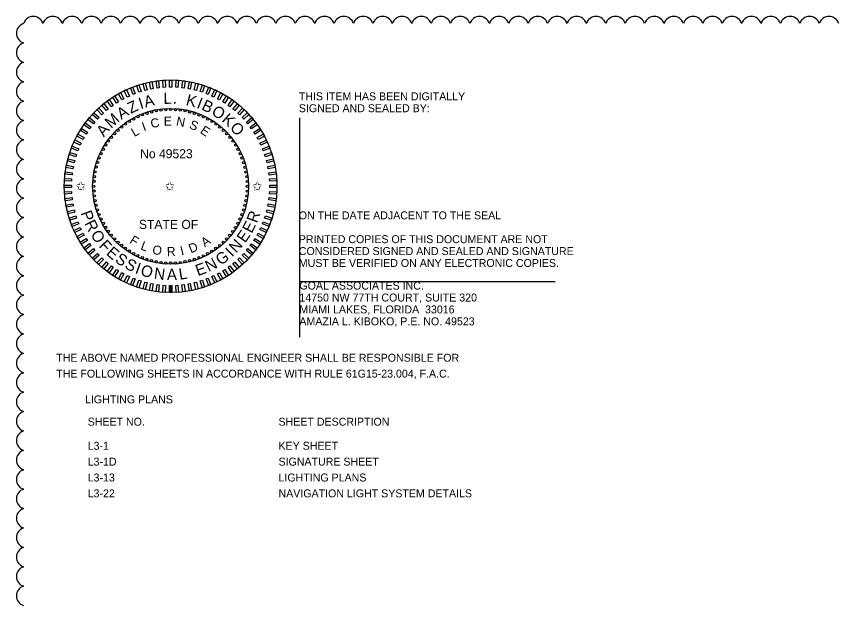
# Model space of a CAD drawing. Extents: x -811 to -795.3, y -2245.7 to -2235.4.
# Drawn here: x -810.85 to -803.6, y -2240.63 to -2235.44 of the extents above; entities that cross this region are included whole.
import ezdxf

# ---------------------------------------------------------------- set-up
doc = ezdxf.new("R2010")
doc.units = 0
for name, color, linetype in [('PlotBorder_dp', 7, 'Continuous'), ('ScratchEle_dp', 7, 'Continuous'), ('TextMinor', 7, 'Continuous'), ('TextMisc', 7, 'Continuous'), ('TextShtNo', 7, 'Continuous'), ('TextTitle', 7, 'Continuous')]:
    doc.layers.add(name, color=color, linetype=linetype)

msp = doc.modelspace()

# ---------------------------------------------------------------- linework, layer by layer
at = {"layer": 'ScratchEle_dp'}
for centre, start, end in [((-810.7011, -2235.5263), 17.5, 162.5), ((-810.53, -2235.5263), 17.5, 162.5), ((-810.3589, -2235.5263), 17.5, 162.5), ((-810.1878, -2235.5263), 17.5, 162.5), ((-810.0167, -2235.5263), 17.5, 162.5), ((-809.8455, -2235.5263), 17.5, 162.5), ((-809.6744, -2235.5263), 17.5, 162.5), ((-809.5033, -2235.5263), 17.5, 162.5), ((-809.3322, -2235.5263), 17.5, 162.5), ((-809.161, -2235.5263), 17.5, 162.5), ((-808.9899, -2235.5263), 17.5, 162.5), ((-808.8188, -2235.5263), 17.5, 162.5), ((-808.6477, -2235.5263), 17.5, 162.5), ((-808.4766, -2235.5263), 17.5, 162.5), ((-808.3054, -2235.5263), 17.5, 162.5), ((-808.1343, -2235.5263), 17.5, 162.5), ((-807.9632, -2235.5263), 17.5, 162.5), ((-807.7921, -2235.5263), 17.5, 162.5), ((-807.6209, -2235.5263), 17.5, 162.5), ((-807.4498, -2235.5263), 17.5, 162.5), ((-807.2787, -2235.5263), 17.5, 162.5), ((-807.1076, -2235.5263), 17.5, 162.5), ((-806.9364, -2235.5263), 17.5, 162.5), ((-806.7653, -2235.5263), 17.5, 162.5), ((-806.5942, -2235.5263), 17.5, 162.5), ((-806.4231, -2235.5263), 17.5, 162.5), ((-806.252, -2235.5263), 17.5, 162.5), ((-806.0808, -2235.5263), 17.5, 162.5), ((-805.9097, -2235.5263), 17.5, 162.5), ((-805.7386, -2235.5263), 17.5, 162.5), ((-805.5675, -2235.5263), 17.5, 162.5), ((-805.3963, -2235.5263), 17.5, 162.5), ((-805.2252, -2235.5263), 17.5, 162.5), ((-805.0541, -2235.5263), 17.5, 162.5), ((-804.883, -2235.5263), 17.5, 162.5), ((-804.7119, -2235.5263), 17.5, 162.5), ((-804.5407, -2235.5263), 17.5, 162.5), ((-804.3696, -2235.5263), 17.5, 162.5), ((-804.1985, -2235.5263), 17.5, 162.5), ((-804.0274, -2235.5263), 17.5, 162.5), ((-803.8562, -2235.5263), 17.5, 162.5), ((-803.6851, -2235.5263), 17.5, 162.5), ((-810.7597, -2235.5849), 107.5, 252.5), ((-810.7597, -2235.7561), 107.5, 252.5), ((-810.7597, -2235.9272), 107.5, 252.5), ((-810.7597, -2236.0983), 107.5, 252.5), ((-810.7597, -2236.2694), 107.5, 252.5), ((-810.7597, -2236.4405), 107.5, 252.5), ((-810.7597, -2236.6117), 107.5, 252.5), ((-810.7597, -2236.7828), 107.5, 252.5), ((-810.7597, -2236.9539), 107.5, 252.5), ((-810.7597, -2237.125), 107.5, 252.5), ((-810.7597, -2237.2962), 107.5, 252.5), ((-810.7597, -2237.4673), 107.5, 252.5), ((-810.7597, -2237.6384), 107.5, 252.5), ((-810.7597, -2237.8095), 107.5, 252.5), ((-810.7597, -2237.9806), 107.5, 252.5), ((-810.7597, -2238.1518), 107.5, 252.5), ((-810.7597, -2238.3229), 107.5, 252.5), ((-810.7597, -2238.494), 107.5, 252.5), ((-810.7597, -2238.6651), 107.5, 252.5), ((-810.7597, -2238.8363), 107.5, 252.5), ((-810.7597, -2239.0074), 107.5, 252.5), ((-810.7597, -2239.1785), 107.5, 252.5), ((-810.7597, -2239.3496), 107.5, 252.5), ((-810.7597, -2239.5207), 107.5, 252.5), ((-810.7597, -2239.6919), 107.5, 252.5), ((-810.7597, -2239.863), 107.5, 252.5), ((-810.7597, -2240.0341), 107.5, 252.5), ((-810.7597, -2240.2052), 107.5, 252.5), ((-810.7597, -2240.3764), 107.5, 252.5), ((-810.7597, -2240.5475), 107.5, 252.5)]:
    msp.add_arc(centre, 0.0897, start, end, dxfattribs=at)
at = {"layer": 'TextMinor'}
for radius in [0.9375, 0.6875]:
    msp.add_circle((-809.4901, -2236.9348), radius, dxfattribs=at)
at = {"layer": 'TextShtNo'}
for p, q in [((-809.5001, -2237.8724), (-809.5003, -2237.8099)), ((-809.4901, -2237.8723), (-809.4903, -2237.8098)), ((-809.4801, -2237.8723), (-809.4803, -2237.8098))]:
    msp.add_line(p, q, dxfattribs=at)
for points in [[(-809.7508, -2236.0995), (-809.77, -2236.1057), (-809.7893, -2236.0463), (-809.7701, -2236.0401)], [(-809.6979, -2236.0847), (-809.7174, -2236.0898), (-809.7329, -2236.0293), (-809.7134, -2236.0243)], [(-809.6441, -2236.0734), (-809.6639, -2236.0772), (-809.6756, -2236.0158), (-809.6558, -2236.012)], [(-809.5897, -2236.0654), (-809.6097, -2236.0679), (-809.6175, -2236.006), (-809.5975, -2236.0035)], [(-809.5349, -2236.0609), (-809.555, -2236.0621), (-809.559, -2235.9998), (-809.5388, -2235.9986)], [(-809.4799, -2236.0598), (-809.5001, -2236.0598), (-809.5001, -2235.9974), (-809.4799, -2235.9974)], [(-809.425, -2236.0622), (-809.4452, -2236.0609), (-809.4412, -2235.9986), (-809.4211, -2235.9998)], [(-809.3703, -2236.068), (-809.3904, -2236.0654), (-809.3825, -2236.0035), (-809.3625, -2236.006)], [(-809.3162, -2236.0772), (-809.336, -2236.0734), (-809.3243, -2236.0121), (-809.3045, -2236.0159)], [(-809.2626, -2236.0898), (-809.2822, -2236.0848), (-809.2667, -2236.0243), (-809.2471, -2236.0293)], [(-809.21, -2236.1058), (-809.2292, -2236.0995), (-809.2099, -2236.0401), (-809.1907, -2236.0464)], [(-809.9027, -2236.1631), (-809.9204, -2236.1728), (-809.9505, -2236.1181), (-809.9328, -2236.1084)], [(-809.8535, -2236.1387), (-809.8717, -2236.1473), (-809.8983, -2236.0908), (-809.8801, -2236.0822)], [(-809.8028, -2236.1175), (-809.8215, -2236.1249), (-809.8445, -2236.0669), (-809.8258, -2236.0594)], [(-809.1585, -2236.125), (-809.1773, -2236.1176), (-809.1543, -2236.0595), (-809.1355, -2236.0669)], [(-809.1083, -2236.1474), (-809.1266, -2236.1388), (-809.1, -2236.0823), (-809.0817, -2236.0909)], [(-809.0596, -2236.1729), (-809.0773, -2236.1632), (-809.0473, -2236.1085), (-809.0296, -2236.1182)], [(-809.9962, -2236.2209), (-810.0125, -2236.2328), (-810.0492, -2236.1823), (-810.0329, -2236.1704)], [(-809.9504, -2236.1906), (-809.9674, -2236.2014), (-810.0009, -2236.1486), (-809.9838, -2236.1378)], [(-809.0127, -2236.2015), (-809.0297, -2236.1906), (-808.9962, -2236.1379), (-808.9792, -2236.1487)], [(-808.9676, -2236.2329), (-808.9839, -2236.221), (-808.9472, -2236.1705), (-808.9308, -2236.1824)], [(-810.0817, -2236.29), (-810.0964, -2236.3038), (-810.1392, -2236.2583), (-810.1244, -2236.2445)], [(-810.04, -2236.2541), (-810.0556, -2236.267), (-810.0954, -2236.2189), (-810.0798, -2236.206)], [(-808.9245, -2236.2671), (-808.9401, -2236.2542), (-808.9003, -2236.2061), (-808.8847, -2236.219)], [(-808.8837, -2236.3039), (-808.8984, -2236.2901), (-808.8557, -2236.2446), (-808.841, -2236.2584)], [(-810.1579, -2236.3692), (-810.1707, -2236.3848), (-810.2188, -2236.345), (-810.206, -2236.3294)], [(-810.121, -2236.3284), (-810.1348, -2236.3431), (-810.1804, -2236.3004), (-810.1665, -2236.2857)], [(-808.8453, -2236.3432), (-808.8591, -2236.3285), (-808.8136, -2236.2858), (-808.7998, -2236.3005)], [(-808.8094, -2236.3849), (-808.8223, -2236.3694), (-808.7742, -2236.3295), (-808.7613, -2236.3451)], [(-810.192, -2236.4122), (-810.2039, -2236.4286), (-810.2544, -2236.3919), (-810.2426, -2236.3755)], [(-808.7762, -2236.4287), (-808.7881, -2236.4124), (-808.7376, -2236.3757), (-808.7257, -2236.392)], [(-810.252, -2236.5043), (-810.2617, -2236.522), (-810.3164, -2236.492), (-810.3067, -2236.4743)], [(-810.2235, -2236.4574), (-810.2343, -2236.4744), (-810.287, -2236.4409), (-810.2762, -2236.4239)], [(-808.7459, -2236.4746), (-808.7567, -2236.4575), (-808.7039, -2236.4241), (-808.6931, -2236.4411)], [(-808.7184, -2236.5222), (-808.7281, -2236.5045), (-808.6734, -2236.4744), (-808.6637, -2236.4921)], [(-810.2775, -2236.553), (-810.2861, -2236.5713), (-810.3426, -2236.5447), (-810.334, -2236.5264)], [(-808.694, -2236.5715), (-808.7026, -2236.5532), (-808.6461, -2236.5266), (-808.6375, -2236.5449)], [(-810.3, -2236.6032), (-810.3074, -2236.622), (-810.3654, -2236.599), (-810.358, -2236.5802)], [(-808.6728, -2236.6222), (-808.6802, -2236.6034), (-808.6222, -2236.5804), (-808.6147, -2236.5992)], [(-810.3351, -2236.7073), (-810.3401, -2236.7269), (-810.4006, -2236.7114), (-810.3956, -2236.6918)], [(-810.3192, -2236.6547), (-810.3254, -2236.6739), (-810.3848, -2236.6546), (-810.3786, -2236.6354)], [(-808.6548, -2236.6741), (-808.661, -2236.6549), (-808.6016, -2236.6356), (-808.5954, -2236.6548)], [(-808.64, -2236.7271), (-808.6451, -2236.7075), (-808.5846, -2236.692), (-808.5796, -2236.7115)], [(-810.3477, -2236.7609), (-810.3515, -2236.7807), (-810.4129, -2236.769), (-810.4091, -2236.7492)], [(-808.6287, -2236.7809), (-808.6325, -2236.761), (-808.5711, -2236.7493), (-808.5673, -2236.7692)], [(-810.357, -2236.815), (-810.3595, -2236.8351), (-810.4215, -2236.8272), (-810.4189, -2236.8072)], [(-808.6207, -2236.8353), (-808.6232, -2236.8152), (-808.5613, -2236.8074), (-808.5588, -2236.8274)], [(-810.3652, -2236.9246), (-810.3652, -2236.9448), (-810.4276, -2236.9448), (-810.4276, -2236.9246)], [(-810.3628, -2236.8697), (-810.3641, -2236.8899), (-810.4264, -2236.8859), (-810.4251, -2236.8658)], [(-808.6162, -2236.89), (-808.6174, -2236.8699), (-808.5551, -2236.866), (-808.5539, -2236.8861)], [(-808.6151, -2236.945), (-808.6151, -2236.9248), (-808.5527, -2236.9248), (-808.5527, -2236.945)], [(-810.3641, -2236.9796), (-810.3628, -2236.9997), (-810.4251, -2237.0037), (-810.4264, -2236.9835)], [(-808.6175, -2236.9999), (-808.6162, -2236.9798), (-808.5539, -2236.9837), (-808.5551, -2237.0039)], [(-810.3595, -2237.0344), (-810.357, -2237.0544), (-810.4189, -2237.0622), (-810.4215, -2237.0422)], [(-808.6233, -2237.0546), (-808.6207, -2237.0346), (-808.5588, -2237.0424), (-808.5613, -2237.0624)], [(-810.3516, -2237.0888), (-810.3478, -2237.1086), (-810.4091, -2237.1203), (-810.4129, -2237.1005)], [(-808.6325, -2237.1088), (-808.6287, -2237.089), (-808.5674, -2237.1007), (-808.5712, -2237.1205)], [(-810.3402, -2237.1426), (-810.3352, -2237.1621), (-810.3957, -2237.1776), (-810.4007, -2237.1581)], [(-810.3255, -2237.1955), (-810.3192, -2237.2147), (-810.3786, -2237.234), (-810.3849, -2237.2148)], [(-808.6611, -2237.2149), (-808.6548, -2237.1957), (-808.5954, -2237.215), (-808.6017, -2237.2342)], [(-808.6451, -2237.1623), (-808.6401, -2237.1427), (-808.5796, -2237.1583), (-808.5846, -2237.1778)], [(-810.3075, -2237.2475), (-810.3, -2237.2662), (-810.3581, -2237.2892), (-810.3655, -2237.2705)], [(-808.6803, -2237.2664), (-808.6729, -2237.2476), (-808.6148, -2237.2706), (-808.6222, -2237.2894)], [(-810.2862, -2237.2982), (-810.2776, -2237.3164), (-810.3341, -2237.343), (-810.3427, -2237.3248)], [(-810.2618, -2237.3474), (-810.2521, -2237.3651), (-810.3068, -2237.3952), (-810.3165, -2237.3775)], [(-808.7282, -2237.3653), (-808.7185, -2237.3476), (-808.6638, -2237.3777), (-808.6735, -2237.3954)], [(-808.7027, -2237.3166), (-808.6941, -2237.2983), (-808.6376, -2237.3249), (-808.6462, -2237.3432)], [(-810.2344, -2237.3951), (-810.2236, -2237.4121), (-810.2763, -2237.4456), (-810.2871, -2237.4285)], [(-808.7568, -2237.4123), (-808.746, -2237.3952), (-808.6932, -2237.4287), (-808.704, -2237.4457)], [(-810.204, -2237.4409), (-810.1922, -2237.4572), (-810.2427, -2237.4939), (-810.2545, -2237.4776)], [(-810.1708, -2237.4847), (-810.158, -2237.5003), (-810.2061, -2237.5401), (-810.2189, -2237.5245)], [(-808.8224, -2237.5004), (-808.8095, -2237.4849), (-808.7614, -2237.5247), (-808.7743, -2237.5402)], [(-808.7882, -2237.4574), (-808.7763, -2237.4411), (-808.7258, -2237.4778), (-808.7377, -2237.4941)], [(-810.135, -2237.5264), (-810.1211, -2237.5411), (-810.1667, -2237.5839), (-810.1805, -2237.5691)], [(-810.0965, -2237.5657), (-810.0818, -2237.5795), (-810.1246, -2237.6251), (-810.1393, -2237.6112)], [(-808.8985, -2237.5797), (-808.8838, -2237.5658), (-808.8411, -2237.6114), (-808.8558, -2237.6252)], [(-808.8592, -2237.5412), (-808.8454, -2237.5265), (-808.7999, -2237.5693), (-808.8137, -2237.584)], [(-810.0557, -2237.6025), (-810.0402, -2237.6154), (-810.08, -2237.6635), (-810.0955, -2237.6507)], [(-810.0127, -2237.6367), (-809.9964, -2237.6486), (-810.0331, -2237.6991), (-810.0494, -2237.6873)], [(-808.984, -2237.6487), (-808.9677, -2237.6369), (-808.931, -2237.6874), (-808.9473, -2237.6992)], [(-808.9402, -2237.6155), (-808.9247, -2237.6027), (-808.8848, -2237.6508), (-808.9004, -2237.6636)], [(-809.9676, -2237.6682), (-809.9505, -2237.679), (-809.984, -2237.7317), (-810.001, -2237.7209)], [(-809.9206, -2237.6967), (-809.9029, -2237.7064), (-809.933, -2237.7611), (-809.9507, -2237.7514)], [(-809.8719, -2237.7222), (-809.8536, -2237.7308), (-809.8802, -2237.7873), (-809.8985, -2237.7787)], [(-809.1268, -2237.7309), (-809.1085, -2237.7223), (-809.0819, -2237.7788), (-809.1002, -2237.7874)], [(-809.0775, -2237.7065), (-809.0598, -2237.6968), (-809.0297, -2237.7515), (-809.0474, -2237.7612)], [(-809.0299, -2237.6791), (-809.0128, -2237.6683), (-808.9794, -2237.721), (-808.9964, -2237.7318)], [(-809.8217, -2237.7447), (-809.8029, -2237.7521), (-809.8259, -2237.8101), (-809.8447, -2237.8027)], [(-809.7702, -2237.7639), (-809.751, -2237.7701), (-809.7703, -2237.8295), (-809.7895, -2237.8233)], [(-809.7176, -2237.7798), (-809.698, -2237.7848), (-809.7136, -2237.8453), (-809.7331, -2237.8403)], [(-809.6641, -2237.7924), (-809.6443, -2237.7962), (-809.656, -2237.8576), (-809.6758, -2237.8538)], [(-809.3362, -2237.7963), (-809.3163, -2237.7925), (-809.3046, -2237.8538), (-809.3245, -2237.8576)], [(-809.2824, -2237.7849), (-809.2628, -2237.7799), (-809.2473, -2237.8404), (-809.2668, -2237.8454)], [(-809.2294, -2237.7702), (-809.2102, -2237.7639), (-809.1909, -2237.8233), (-809.2101, -2237.8296)], [(-809.1775, -2237.7522), (-809.1587, -2237.7447), (-809.1357, -2237.8028), (-809.1545, -2237.8102)], [(-809.6099, -2237.8017), (-809.5899, -2237.8042), (-809.5977, -2237.8662), (-809.6177, -2237.8636)], [(-809.5552, -2237.8075), (-809.5351, -2237.8088), (-809.539, -2237.8711), (-809.5592, -2237.8698)], [(-809.5003, -2237.8099), (-809.4801, -2237.8099), (-809.4801, -2237.8723), (-809.5003, -2237.8723)], [(-809.4453, -2237.8088), (-809.4252, -2237.8075), (-809.4213, -2237.8698), (-809.4414, -2237.8711)], [(-809.3906, -2237.8042), (-809.3705, -2237.8017), (-809.3627, -2237.8636), (-809.3827, -2237.8662)]]:
    msp.add_lwpolyline(points, close=True, dxfattribs=at)
for centre in [(-809.6581, -2236.2785), (-809.6165, -2236.2692), (-809.5745, -2236.2626), (-809.5321, -2236.2587), (-809.4896, -2236.2574), (-809.447, -2236.2587), (-809.4047, -2236.2628), (-809.3626, -2236.2695), (-809.3211, -2236.2788), (-809.816, -2236.3409), (-809.7781, -2236.3216), (-809.739, -2236.3047), (-809.6989, -2236.2903), (-809.2802, -2236.2907), (-809.2402, -2236.3051), (-809.2012, -2236.3221), (-809.1633, -2236.3414), (-809.9215, -2236.4125), (-809.8879, -2236.3864), (-809.8527, -2236.3625), (-809.1266, -2236.3631), (-809.0915, -2236.3871), (-809.0579, -2236.4132), (-809.9836, -2236.4707), (-809.9535, -2236.4406), (-809.026, -2236.4414), (-808.9959, -2236.4715), (-810.0618, -2236.5713), (-810.0379, -2236.5362), (-810.0118, -2236.5026), (-808.9678, -2236.5034), (-808.9417, -2236.5371), (-808.9178, -2236.5723), (-810.0835, -2236.608), (-808.8962, -2236.6089), (-810.1198, -2236.6849), (-810.1029, -2236.6459), (-808.8769, -2236.6469), (-808.86, -2236.686), (-810.1462, -2236.7658), (-810.1343, -2236.7249), (-808.8456, -2236.726), (-808.8338, -2236.7669), (-810.1622, -2236.8494), (-810.1555, -2236.8073), (-808.8245, -2236.8084), (-808.8179, -2236.8505), (-810.1676, -2236.9343), (-810.1662, -2236.8917), (-808.814, -2236.8928), (-810.1663, -2236.9768), (-808.814, -2236.9779), (-808.8127, -2236.9354), (-810.1623, -2237.0192), (-810.1557, -2237.0612), (-808.8248, -2237.0623), (-808.8181, -2237.0203), (-810.1464, -2237.1028), (-810.1346, -2237.1436), (-808.846, -2237.1447), (-808.8341, -2237.1038), (-810.1202, -2237.1837), (-810.1034, -2237.2228), (-808.8774, -2237.2238), (-808.8604, -2237.1847), (-810.0841, -2237.2607), (-810.0624, -2237.2974), (-808.8967, -2237.2617), (-810.0385, -2237.3326), (-810.0125, -2237.3662), (-808.9685, -2237.3671), (-808.9424, -2237.3335), (-808.9184, -2237.2983), (-809.9844, -2237.3982), (-809.9543, -2237.4283), (-809.0268, -2237.4291), (-808.9967, -2237.399), (-809.9224, -2237.4565), (-809.8888, -2237.4826), (-809.8536, -2237.5065), (-809.1276, -2237.5071), (-809.0924, -2237.4832), (-809.0587, -2237.4572), (-809.817, -2237.5282), (-809.7791, -2237.5476), (-809.74, -2237.5645), (-809.7, -2237.579), (-809.2813, -2237.5793), (-809.2413, -2237.5649), (-809.2022, -2237.5481), (-809.1642, -2237.5288), (-809.6591, -2237.5909), (-809.6176, -2237.6002), (-809.5756, -2237.6069), (-809.5332, -2237.6109), (-809.4901, -2237.6123), (-809.4481, -2237.611), (-809.4058, -2237.607), (-809.3637, -2237.6004), (-809.3222, -2237.5911)]:
    msp.add_circle(centre, 0.01, dxfattribs=at)
at = {"layer": 'TextTitle'}
for p, q in [((-808.3546, -2236.3314), (-808.3546, -2238.2661)), ((-808.3546, -2237.7761), (-806.0979, -2237.7761))]:
    msp.add_line(p, q, dxfattribs=at)

# ---------------------------------------------------------------- texts
at = {"layer": 'PlotBorder_dp'}
for s, p in [('THIS ITEM HAS BEEN DIGITALLY', (-808.3596, -2236.1763)), ('SIGNED AND SEALED BY:', (-808.3596, -2236.2813)), ('ON THE DATE ADJACENT TO THE SEAL', (-808.3596, -2237.2263)), ('PRINTED COPIES OF THIS DOCUMENT ARE NOT ', (-808.3596, -2237.4363)), ('CONSIDERED SIGNED AND SEALED AND SIGNATURE ', (-808.3596, -2237.5413)), ('MUST BE VERIFIED ON ANY ELECTRONIC COPIES.', (-808.3596, -2237.6463)), ('GOAL ASSOCIATES INC.', (-808.3546, -2237.8461)), ('14750 NW 77TH COURT, SUITE 320', (-808.3546, -2237.9511)), ('MIAMI LAKES, FLORIDA  33016', (-808.3546, -2238.0561)), ('AMAZIA L. KIBOKO, P.E. NO. 49523', (-808.3546, -2238.1611)), ('THE ABOVE NAMED PROFESSIONAL ENGINEER SHALL BE RESPONSIBLE FOR ', (-810.4987, -2238.4823)), ('THE FOLLOWING SHEETS IN ACCORDANCE WITH RULE 61G15-23.004, F.A.C.', (-810.4987, -2238.6223)), ('LIGHTING PLANS', (-810.245, -2238.8493))]:
    msp.add_text(s, height=0.07, dxfattribs=at).set_placement(p)
at = {"layer": 'TextMisc'}
for s, p in [('SHEET NO.', (-810.2215, -2239.0463)), ('SHEET DESCRIPTION', (-808.5387, -2239.0463)), ('L3-1', (-810.2215, -2239.2585)), ('KEY SHEET', (-808.5387, -2239.2585)), ('L3-1D', (-810.2215, -2239.3985)), ('SIGNATURE SHEET', (-808.5387, -2239.3985)), ('L3-13', (-810.2215, -2239.5385)), ('LIGHTING PLANS', (-808.5387, -2239.5385)), ('L3-22', (-810.2215, -2239.6785)), ('NAVIGATION LIGHT SYSTEM DETAILS', (-808.5387, -2239.6785))]:
    msp.add_text(s, height=0.07, dxfattribs=at).set_placement(p)
at = {"layer": 'TextShtNo'}
for s, height, rotation, p in [('L', 0.1, 0.99956, (-809.5521, -2236.2083)), ('K', 0.1, 345.88231, (-809.3605, -2236.2173)), ('Z', 0.1, 24.97699, (-809.842, -2236.2962)), ('I', 0.1, 17.3791, (-809.7545, -2236.2553)), ('A', 0.1, 13.84591, (-809.7121, -2236.2403)), ('.', 0.1, 354.73644, (-809.4725, -2236.2059)), ('I', 0.1, 338.30858, (-809.267, -2236.2406)), ('B', 0.1, 334.77539, (-809.2247, -2236.2557)), ('A', 0.1, 32.74398, (-809.9251, -2236.3496)), ('O', 0.1, 327.17146, (-809.1372, -2236.2968)), ('M', 0.1, 42.19, (-810.0152, -2236.4289)), ('C', 0.08, 12.20255, (-809.6579, -2236.4232)), ('E', 0.08, 0.41861, (-809.5498, -2236.3997)), ('N', 0.08, 349.29143, (-809.4455, -2236.3983)), ('K', 0.1, 318.5106, (-809.0451, -2236.3572)), ('A', 0.1, 49.957, (-810.0788, -2236.5045)), ('I', 0.08, 20.01168, (-809.7258, -2236.4508)), ('S', 0.08, 337.02207, (-809.3325, -2236.42)), ('E', 0.08, 325.86633, (-809.2358, -2236.4603)), ('O', 0.1, 310.93687, (-808.9729, -2236.4209)), ('L', 0.08, 30.40215, (-809.8093, -2236.5012)), ('P', 0.1, 289.40551, (-810.2848, -2237.1694)), ('R', 0.1, 69.5134, (-808.7299, -2237.2645)), ('R', 0.1, 296.14576, (-810.2518, -2237.2611)), ('E', 0.1, 62.47116, (-808.7761, -2237.3552)), ('O', 0.1, 303.96711, (-810.2003, -2237.3617)), ('E', 0.1, 55.42892, (-808.833, -2237.4396)), ('F', 0.1, 312.62798, (-810.1279, -2237.4637)), ('F', 0.08, 328.72408, (-809.8582, -2237.4314)), ('L', 0.08, 339.29159, (-809.7609, -2237.4905)), ('A', 0.08, 34.49917, (-809.1883, -2237.4742)), ('N', 0.1, 47.17876, (-808.9123, -2237.5287)), ('E', 0.1, 319.07833, (-810.0645, -2237.5321)), ('O', 0.08, 349.68206, (-809.6562, -2237.5302)), ('R', 0.08, 2.33977, (-809.5217, -2237.5521)), ('I', 0.08, 14.20366, (-809.3941, -2237.5454)), ('D', 0.08, 22.01279, (-809.312, -2237.5267)), ('I', 0.1, 43.64556, (-808.9499, -2237.5632)), ('S', 0.1, 326.12056, (-809.9869, -2237.598)), ('S', 0.1, 333.193, (-809.9015, -2237.6541)), ('N', 0.1, 26.86136, (-809.1544, -2237.6924)), ('G', 0.1, 35.11153, (-809.0492, -2237.6364)), ('I', 0.1, 340.26543, (-809.8098, -2237.6993)), ('O', 0.1, 343.79863, (-809.7621, -2237.7175)), ('E', 0.1, 19.81912, (-809.2498, -2237.7278)), ('N', 0.1, 352.45949, (-809.6411, -2237.7495)), ('A', 0.1, 0.70966, (-809.5227, -2237.7628)), ('L', 0.1, 8.47665, (-809.4105, -2237.7596))]:
    msp.add_text(s, height=height, rotation=rotation, dxfattribs=at).set_placement(p)
for s, p in [('No 49523', (-809.7591, -2236.6876)), ('✩', (-810.3251, -2236.9728)), ('✩', (-809.5404, -2236.9728)), ('✩', (-808.7685, -2236.9728)), ('STATE OF', (-809.7698, -2237.311))]:
    msp.add_text(s, height=0.08, dxfattribs=at).set_placement(p)

doc.saveas('drawing.dxf')
